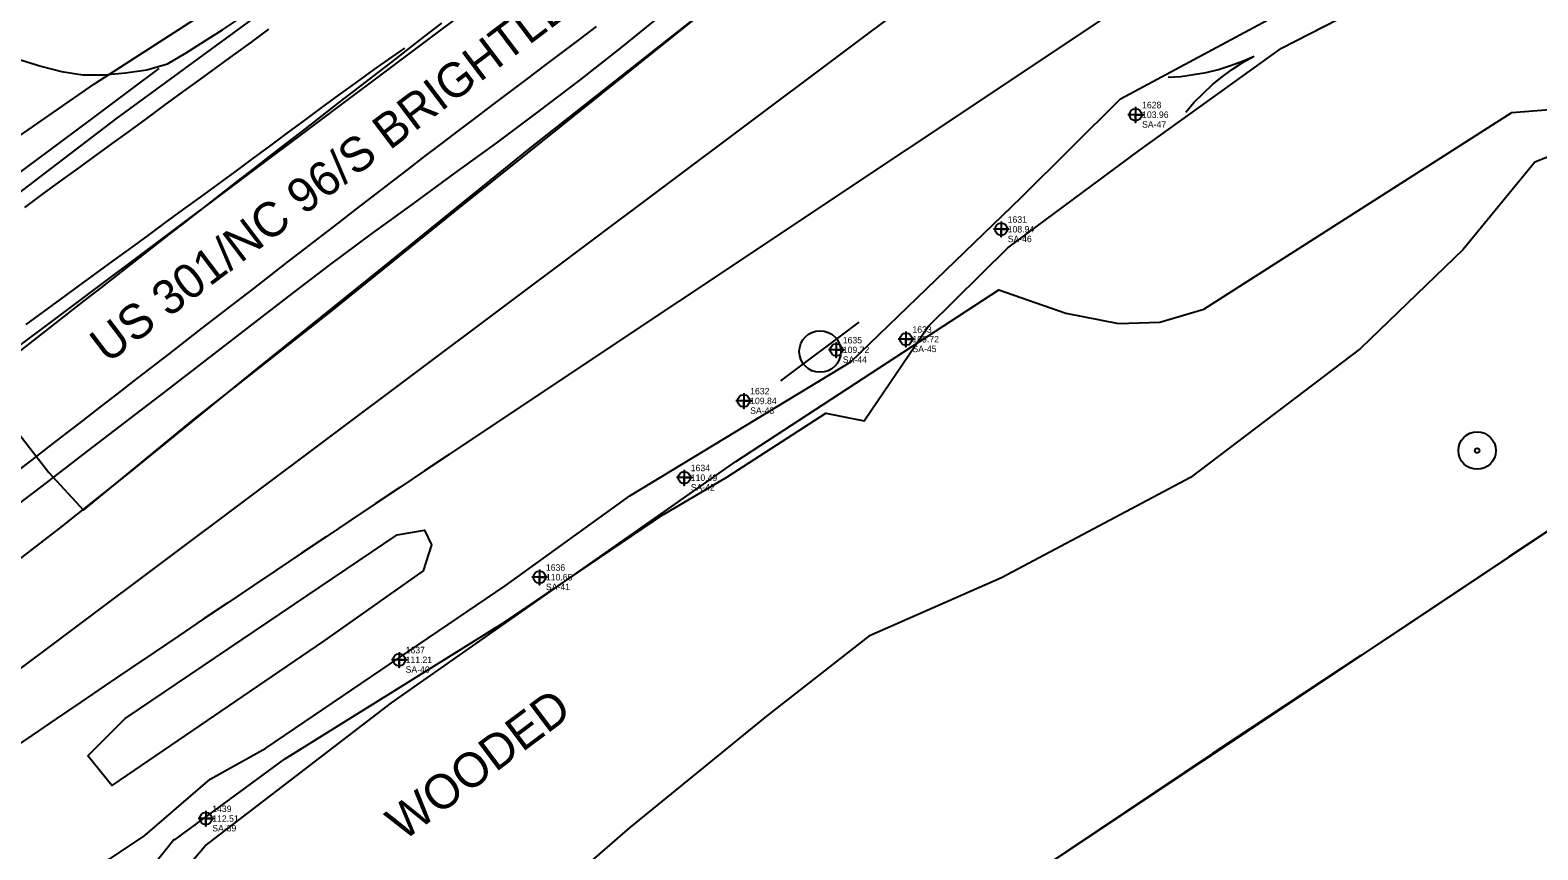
# Model space of a CAD drawing. Extents: x 2186615 to 2188822, y 629899 to 631820.
# Drawn here: x 2187474 to 2187648.6, y 630571.8 to 630666.8 of the extents above; entities that cross this region are included whole.
import ezdxf

# ---------------------------------------------------------------- set-up
doc = ezdxf.new("R2010")
doc.units = 0
for name, color, linetype in [('Exist Environmental Wetland Boundary Cogo Comment', 7, 'Continuous'), ('Exist Environmental Wetland Boundary Cogo Elevation', 7, 'Continuous'), ('Exist Environmental Wetland Boundary Cogo Number', 7, 'Continuous'), ('Exist Environmental Wetland Boundary Cogo Point CELL', 7, 'Continuous'), ('Exist Guardrail', 7, 'Continuous'), ('Exist Horizontal Alignment', 7, 'Continuous'), ('Exist Hydro Jurisdictional Stream or Body of Water', 7, 'Continuous'), ('Exist Hydro Stream Flow Arrow CELL', 7, 'Continuous'), ('Exist Railroads Signal Milepost CELL', 7, 'Continuous'), ('Exist Railroads Standard Gauge', 7, 'Continuous'), ('Exist Right of Way Line', 7, 'Continuous'), ('Exist Roads EOP', 7, 'Continuous'), ('Exist Roads EOP Text', 7, 'Continuous'), ('Exist Roads EOT', 7, 'Continuous'), ('Exist Utilities Sanitary Sewer Forced Main SUE LOS B', 7, 'Continuous'), ('Exist Utilities Telephone Pole CELL', 7, 'Continuous'), ('Exist Utilities Telephone UG FO SUE LOS B', 7, 'Continuous'), ('Exist Utilities Water UG Line SUE LOS B', 7, 'Continuous'), ('Exist Vegetation Woods Line', 7, 'Continuous'), ('Exist Vegetation Woods Line Text', 7, 'Continuous'), ('Scratch_Level_1', 7, 'Continuous')]:
    doc.layers.add(name, color=color, linetype=linetype)

msp = doc.modelspace()

# ---------------------------------------------------------------- linework, layer by layer
at = {"layer": 'Exist Environmental Wetland Boundary Cogo Point CELL'}
for points in [[(2187602.05, 630657.94), (2187602.05, 630656.14), (2187602.05, 630657.04), (2187602.95, 630657.04), (2187601.15, 630657.04)], [(2187586.48, 630644.67), (2187586.48, 630642.87), (2187586.48, 630643.77), (2187587.38, 630643.77), (2187585.58, 630643.77)], [(2187567.38, 630630.68), (2187567.38, 630628.88), (2187567.38, 630629.78), (2187568.28, 630629.78), (2187566.48, 630629.78)], [(2187575.45, 630631.92), (2187575.45, 630630.12), (2187575.45, 630631.02), (2187576.35, 630631.02), (2187574.55, 630631.02)], [(2187556.65, 630624.77), (2187556.65, 630622.97), (2187556.65, 630623.87), (2187557.55, 630623.87), (2187555.75, 630623.87)], [(2187549.77, 630615.87), (2187549.77, 630614.07), (2187549.77, 630614.97), (2187550.67, 630614.97), (2187548.87, 630614.97)], [(2187532.99, 630604.33), (2187532.99, 630602.53), (2187532.99, 630603.43), (2187533.89, 630603.43), (2187532.09, 630603.43)], [(2187516.74, 630594.76), (2187516.74, 630592.96), (2187516.74, 630593.86), (2187517.64, 630593.86), (2187515.84, 630593.86)], [(2187494.34, 630576.36), (2187494.34, 630574.56), (2187494.34, 630575.46), (2187495.24, 630575.46), (2187493.44, 630575.46)]]:
    msp.add_lwpolyline(points, dxfattribs=at)
for centre in [(2187602.05, 630657.04), (2187586.48, 630643.77), (2187567.38, 630629.78), (2187575.45, 630631.02), (2187556.65, 630623.87), (2187549.77, 630614.97), (2187532.99, 630603.43), (2187516.74, 630593.86), (2187494.34, 630575.46)]:
    msp.add_circle(centre, 0.703, dxfattribs=at)
at = {"layer": 'Exist Guardrail'}
msp.add_lwpolyline([(2187600.82, 630707.03), (2187590.08, 630698.8), (2187578.34, 630689.84), (2187562.72, 630677.51), (2187547.73, 630665.68), (2187531.87, 630653.17), (2187514.82, 630639.34), (2187500.32, 630627.65), (2187485.34, 630615.46), (2187477.41, 630609.1), (2187466.89, 630601.03), (2187451.76, 630589.34), (2187434.11, 630575.84), (2187413.64, 630560.33)], dxfattribs=at)
at = {"layer": 'Exist Horizontal Alignment'}
msp.add_line((2187136.41, 630378.11), (2188520.86, 631416.04), dxfattribs=at)
at = {"layer": 'Exist Hydro Jurisdictional Stream or Body of Water'}
for points in [[(2187449.56, 630557.04), (2187457.67, 630561.55), (2187469.6, 630560.19), (2187477.83, 630568.81), (2187483.29, 630570.83), (2187487.27, 630573.49), (2187494.84, 630580), (2187501.28, 630583.62), (2187529.01, 630602.42), (2187543.47, 630612.86), (2187569.07, 630628.39), (2187588.84, 630647.49), (2187600.3, 630658.9), (2187631.69, 630675.75), (2187643.77, 630689.68), (2187651.01, 630689.99), (2187663.15, 630692.5)], [(2187447.83, 630554.37), (2187455.66, 630557.6), (2187469.6, 630555.05), (2187473.86, 630558.86), (2187485.6, 630566.69), (2187490.63, 630573.04), (2187490.78, 630573.03), (2187503.45, 630582.34), (2187528.93, 630598.21), (2187547.35, 630610.71), (2187554.69, 630615.02), (2187566.17, 630622.44), (2187570.59, 630621.55), (2187578.03, 630632.5), (2187587.26, 630641.63), (2187602.46, 630652.89), (2187618.95, 630664.76), (2187633.75, 630672.36)]]:
    msp.add_lwpolyline(points, dxfattribs=at)
at = {"layer": 'Exist Hydro Stream Flow Arrow CELL'}
msp.add_line((2187611.32, 630661.6), (2187611.32, 630661.6), dxfattribs=at)
for points in [[(2187605.83, 630661.41), (2187607.29, 630661.47), (2187608.77, 630661.69), (2187610.23, 630661.94), (2187611.64, 630662.29), (2187613.05, 630662.73), (2187614.45, 630663.25), (2187615.79, 630663.84)], [(2187607.88, 630657.32), (2187608.81, 630658.45), (2187609.87, 630659.5), (2187610.94, 630660.53), (2187612.06, 630661.44), (2187613.26, 630662.31), (2187614.52, 630663.12), (2187615.79, 630663.84)]]:
    msp.add_lwpolyline(points, dxfattribs=at)
at = {"layer": 'Exist Railroads Signal Milepost CELL'}
for radius in [2.17, 0.264]:
    msp.add_circle((2187641.61, 630618.11), radius, dxfattribs=at)
at = {"layer": 'Exist Railroads Standard Gauge'}
msp.add_lwpolyline([(2187662.94, 630617.46), (2187645.28, 630605.8), (2187628.12, 630594.35), (2187610.96, 630583.01), (2187591.05, 630569.62)], dxfattribs=at)
at = {"layer": 'Exist Right of Way Line'}
for p, q in [((2187154.4, 630354.1), (2188538.85, 631392.04)), ((2187522.53, 630617.66), (2187850.44, 630836.28))]:
    msp.add_line(p, q, dxfattribs=at)
msp.add_arc((2191071.84, 625294.06), 6398.3, 123.691884, 125.65722, dxfattribs=at)
at = {"layer": 'Exist Roads EOP'}
for points in [[(2187461.17, 630672.23), (2187462.73, 630670.28), (2187464.48, 630668.51), (2187466.27, 630666.78), (2187468.31, 630665.35), (2187470.54, 630664.28), (2187472.86, 630663.4), (2187475.23, 630662.66), (2187477.64, 630662.06), (2187480.09, 630661.67), (2187482.58, 630661.66), (2187485.06, 630661.91), (2187487.53, 630662.24), (2187489.92, 630662.94), (2187492.07, 630664.22), (2187494.19, 630665.55), (2187496.29, 630666.9), (2187498.38, 630668.28), (2187500.44, 630669.69), (2187502.48, 630671.13), (2187504.52, 630672.59), (2187506.55, 630674.04), (2187508.59, 630675.49), (2187509.03, 630675.81)], [(2187546.96, 630668.51), (2187542.31, 630664.71), (2187537.6, 630660.99), (2187532.82, 630657.37), (2187528, 630653.8), (2187523.16, 630650.25), (2187518.31, 630646.72), (2187513.46, 630643.19), (2187508.65, 630639.61), (2187503.87, 630635.97), (2187499.12, 630632.31), (2187494.37, 630628.64), (2187489.62, 630624.97), (2187484.87, 630621.31), (2187480.11, 630617.65), (2187475.35, 630614), (2187470.58, 630610.36)], [(2187432.98, 630620.36), (2187437.76, 630623.99), (2187442.54, 630627.62), (2187447.32, 630631.24), (2187452.11, 630634.86), (2187456.9, 630638.47), (2187461.7, 630642.07), (2187466.51, 630645.67), (2187471.32, 630649.25), (2187476.13, 630652.83), (2187480.94, 630656.41), (2187485.75, 630660), (2187488.95, 630662.4)]]:
    msp.add_lwpolyline(points, dxfattribs=at)
at = {"layer": 'Exist Roads EOT'}
for points in [[(2187539.57, 630667.28), (2187537.58, 630665.77), (2187535.59, 630664.27), (2187533.59, 630662.76), (2187531.6, 630661.25), (2187529.61, 630659.74), (2187527.61, 630658.23), (2187525.62, 630656.72), (2187523.62, 630655.22), (2187521.63, 630653.71), (2187519.64, 630652.19), (2187517.66, 630650.67), (2187515.68, 630649.14), (2187513.7, 630647.61), (2187511.73, 630646.08), (2187509.75, 630644.55), (2187507.77, 630643.03), (2187505.79, 630641.5), (2187503.81, 630639.97), (2187501.83, 630638.44), (2187499.85, 630636.91), (2187497.88, 630635.39), (2187495.9, 630633.86), (2187493.92, 630632.32), (2187491.95, 630630.79), (2187489.97, 630629.26), (2187488, 630627.73), (2187486.02, 630626.2), (2187484.05, 630624.66), (2187482.07, 630623.13), (2187480.1, 630621.6), (2187478.12, 630620.07), (2187476.14, 630618.53), (2187474.17, 630617.01), (2187472.19, 630615.48)], [(2187472.36, 630629.29), (2187474.33, 630630.83), (2187476.3, 630632.37), (2187478.28, 630633.91), (2187480.25, 630635.45), (2187482.22, 630636.98), (2187484.19, 630638.52), (2187486.16, 630640.06), (2187488.13, 630641.6), (2187490.1, 630643.14), (2187492.07, 630644.67), (2187494.04, 630646.21), (2187496.01, 630647.75), (2187497.99, 630649.29), (2187499.96, 630650.82), (2187501.93, 630652.35), (2187503.91, 630653.89), (2187505.89, 630655.42), (2187507.86, 630656.95), (2187509.84, 630658.48), (2187511.81, 630660.01), (2187513.79, 630661.54), (2187515.77, 630663.07), (2187517.74, 630664.61), (2187519.72, 630666.14), (2187521.69, 630667.67)], [(2187473.37, 630646.3), (2187475.39, 630647.78), (2187477.41, 630649.25), (2187479.43, 630650.73), (2187481.45, 630652.2), (2187483.47, 630653.67), (2187485.49, 630655.15), (2187487.51, 630656.62), (2187489.53, 630658.1), (2187491.54, 630659.57), (2187493.56, 630661.05), (2187495.58, 630662.52), (2187497.6, 630663.99), (2187499.62, 630665.47), (2187501.64, 630666.94)], [(2187473.53, 630632.72), (2187475.55, 630634.2), (2187477.56, 630635.68), (2187479.58, 630637.15), (2187481.6, 630638.63), (2187483.62, 630640.1), (2187485.64, 630641.58), (2187487.66, 630643.05), (2187489.68, 630644.53), (2187491.69, 630646), (2187493.71, 630647.48), (2187495.73, 630648.95), (2187497.75, 630650.43), (2187499.76, 630651.92), (2187501.77, 630653.4), (2187503.78, 630654.89), (2187505.79, 630656.37), (2187507.8, 630657.86), (2187509.81, 630659.34), (2187511.82, 630660.83), (2187513.85, 630662.3), (2187515.89, 630663.73), (2187517.39, 630664.76)]]:
    msp.add_lwpolyline(points, dxfattribs=at)
at = {"layer": 'Exist Utilities Sanitary Sewer Forced Main SUE LOS B'}
msp.add_lwpolyline([(2187442.18, 630656.68), (2187443.57, 630654.02), (2187450.8, 630648.53), (2187457.87, 630639.18), (2187476.15, 630615.58), (2187480.17, 630611.22), (2187493.05, 630621.78), (2187508.78, 630634.21), (2187523.23, 630645.86), (2187552.85, 630669.64), (2187578.51, 630689.58), (2187603.2, 630710), (2187618.89, 630721.49), (2187639.4, 630737.18), (2187658.16, 630751.34)], dxfattribs=at)
at = {"layer": 'Exist Utilities Telephone Pole CELL'}
for p, q in [((2187560.95, 630626.19), (2187570.03, 630632.98)), ((2187565.5, 630629.59), (2187565.5, 630629.59))]:
    msp.add_line(p, q, dxfattribs=at)
msp.add_circle((2187565.5, 630629.59), 2.41, dxfattribs=at)
at = {"layer": 'Exist Utilities Telephone UG FO SUE LOS B'}
msp.add_lwpolyline([(2187221.79, 630477.44), (2187244.49, 630488.55), (2187260.77, 630497.3), (2187273.17, 630505), (2187293.43, 630515), (2187319.92, 630532.54), (2187378.48, 630575.93), (2187483.97, 630656.58), (2187503.96, 630671.26), (2187608.06, 630745.86)], dxfattribs=at)
at = {"layer": 'Exist Utilities Water UG Line SUE LOS B'}
msp.add_lwpolyline([(2187356.85, 630563.99), (2187378.55, 630580.27), (2187392.02, 630590.2), (2187407.32, 630601.82), (2187422.62, 630614.3), (2187442.82, 630630.04), (2187465.16, 630649.35), (2187481.46, 630660.64), (2187503.4, 630674.82), (2187521.29, 630686.41), (2187544.6, 630702.68), (2187560.64, 630714.46), (2187571.68, 630722.27), (2187591.48, 630736.67), (2187622.28, 630760.13), (2187641.11, 630774.22), (2187678.52, 630802.38)], dxfattribs=at)
at = {"layer": 'Exist Vegetation Woods Line'}
for points in [[(2187492.45, 630570.17), (2187494.25, 630572.31), (2187515.86, 630588.87), (2187555.74, 630616.85), (2187586.21, 630636.73), (2187593.97, 630634.03), (2187600.08, 630632.83), (2187604.87, 630632.98), (2187609.94, 630634.52), (2187645.64, 630657.31), (2187667.13, 630659.01), (2187648.28, 630651.55)], [(2187648.28, 630651.55), (2187640, 630641.4), (2187628.1, 630629.93), (2187608.39, 630614.98), (2187586.53, 630603.34), (2187571.13, 630596.6), (2187559.28, 630587.31), (2187543.45, 630574.43), (2187525.86, 630559.12)], [(2187485.02, 630587.05), (2187516.51, 630608.34), (2187519.67, 630608.9), (2187520.5, 630607.2), (2187519.53, 630604.17), (2187507.98, 630596.01), (2187483.47, 630579.28), (2187480.66, 630582.72), (2187485.02, 630587.05)]]:
    msp.add_lwpolyline(points, dxfattribs=at)
at = {"layer": 'Scratch_Level_1'}
msp.add_line((2187565.8, 630552.76), (2187893.71, 630771.38), dxfattribs=at)

# ---------------------------------------------------------------- texts
at = {"layer": 'Exist Environmental Wetland Boundary Cogo Comment'}
for s, p in [('SA-47', (2187602.8, 630655.54)), ('SA-46', (2187587.23, 630642.27)), ('SA-45', (2187576.2, 630629.52)), ('SA-44', (2187568.13, 630628.28)), ('SA-43', (2187557.4, 630622.37)), ('SA-42', (2187550.52, 630613.47)), ('SA-41', (2187533.74, 630601.93)), ('SA-40', (2187517.49, 630592.36)), ('SA-39', (2187495.09, 630573.96))]:
    msp.add_text(s, height=0.75, dxfattribs=at).set_placement(p)
at = {"layer": 'Exist Environmental Wetland Boundary Cogo Elevation'}
for s, p in [('103.96', (2187602.8, 630656.67)), ('108.94', (2187587.23, 630643.39)), ('109.72', (2187576.2, 630630.64)), ('109.72', (2187568.13, 630629.41)), ('109.84', (2187557.4, 630623.49)), ('110.49', (2187550.52, 630614.59)), ('110.65', (2187533.74, 630603.05)), ('111.21', (2187517.49, 630593.48)), ('112.51', (2187495.09, 630575.08))]:
    msp.add_text(s, height=0.75, dxfattribs=at).set_placement(p)
at = {"layer": 'Exist Environmental Wetland Boundary Cogo Number'}
for s, p in [('1628', (2187602.8, 630657.79)), ('1631', (2187587.23, 630644.52)), ('1633', (2187576.2, 630631.77)), ('1635', (2187568.13, 630630.53)), ('1632', (2187557.4, 630624.62)), ('1634', (2187550.52, 630615.72)), ('1636', (2187533.74, 630604.18)), ('1637', (2187517.49, 630594.61)), ('1439', (2187495.09, 630576.21))]:
    msp.add_text(s, height=0.75, dxfattribs=at).set_placement(p)
at = {"layer": 'Exist Roads EOP Text'}
msp.add_text("US 301/NC 96/S BRIGHTLEAF BLVD 28' BST", height=4, rotation=37.1238, dxfattribs=at).set_placement((2187482.93, 630628.1))
at = {"layer": 'Exist Vegetation Woods Line Text'}
msp.add_text('WOODED', height=4, rotation=36.8593, dxfattribs=at).set_placement((2187517.22, 630572.75))

doc.saveas('drawing.dxf')
